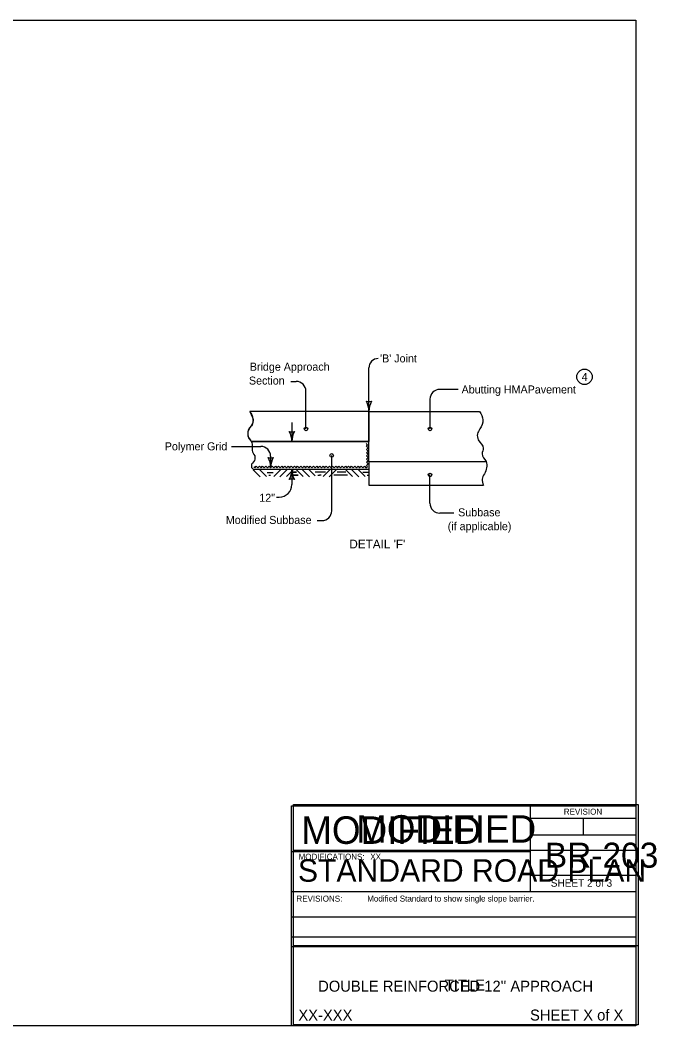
# Model space of a CAD drawing. Extents: x -2134934 to -2124557, y -2139046 to -2134021.
# Drawn here: x -2129429 to -2128157, y -2139046 to -2137036 of the extents above; entities that cross this region are included whole.
import ezdxf

# ---------------------------------------------------------------- set-up
doc = ezdxf.new("R2010")
doc.units = 0
for name, color, linetype in [('BridgeSuperStructureExisting', 7, 'Continuous'), ('Default', 7, 'Continuous'), ('Dimension', 7, 'Continuous'), ('dsnAlignmentCurveData', 7, 'Continuous'), ('dsnAlignmentStation', 7, 'Continuous'), ('DsnShtInsideBorder', 7, 'Continuous'), ('dsnStdLabel', 7, 'Continuous'), ('TC_Barrier', 7, 'Continuous')]:
    doc.layers.add(name, color=color, linetype=linetype)

msp = doc.modelspace()

# ---------------------------------------------------------------- linework, layer by layer
at = {"layer": 'BridgeSuperStructureExisting'}
for p, q in [((-2128732.5, -2137817.8), (-2128732.5, -2137731)), ((-2128888.8, -2137758), (-2128878.2, -2137758)), ((-2128858.4, -2137853), (-2128858.4, -2137777.8)), ((-2128554.4, -2137773.9), (-2128590.9, -2137773.9)), ((-2128610.7, -2137793.7), (-2128610.7, -2137853)), ((-2128732.5, -2137818.3), (-2128970.5, -2137818.3)), ((-2128732.5, -2137818.3), (-2128970.2, -2137818.3)), ((-2128732.5, -2137878.3), (-2128732.5, -2137818.3)), ((-2128732.5, -2137818.3), (-2128511.5, -2137818.3)), ((-2128732.5, -2137818.3), (-2128732.5, -2137878.3)), ((-2128886.6, -2137839.9), (-2128886.6, -2137878.3)), ((-2129007.2, -2137887.9), (-2128948.7, -2137887.9)), ((-2128967.4, -2137878.3), (-2128732.5, -2137878.3)), ((-2128732.5, -2137878.3), (-2128967.4, -2137878.3)), ((-2128732.5, -2137918.3), (-2128732.5, -2137878.3)), ((-2128928.9, -2137907.7), (-2128928.9, -2137929.9)), ((-2128806.9, -2138016.4), (-2128806.9, -2137905.9)), ((-2128732.9, -2137906.8), (-2128732.9, -2137906.8)), ((-2128732.5, -2137918.3), (-2128498.7, -2137918.3)), ((-2128732.5, -2137918.3), (-2128732.5, -2137965.6)), ((-2128963.8, -2137934.4), (-2128949.8, -2137948.4)), ((-2128732.9, -2137934.2), (-2128960.5, -2137934.2)), ((-2128930, -2137934.2), (-2128958.4, -2137934.2)), ((-2128951.4, -2137934.2), (-2128937.4, -2137948.2)), ((-2128924, -2137940.4), (-2128935.9, -2137940.4)), ((-2128932.4, -2137945.3), (-2128929.1, -2137945.3)), ((-2128930, -2137934.2), (-2128930, -2137934.2)), ((-2128831.5, -2137934.2), (-2128930, -2137934.2)), ((-2128930, -2137934.2), (-2128930, -2137934.2)), ((-2128908.6, -2137934.2), (-2128922.6, -2137948.2)), ((-2128896.3, -2137934.4), (-2128910.3, -2137948.4)), ((-2128883.4, -2137934.2), (-2128897.4, -2137948.2)), ((-2128887.8, -2137945.4), (-2128873.7, -2137945.4)), ((-2128887.8, -2137945.4), (-2128873.7, -2137945.4)), ((-2128873.7, -2137945.4), (-2128887.8, -2137945.4)), ((-2128873.7, -2137945.4), (-2128887.8, -2137945.4)), ((-2128886.6, -2137933.9), (-2128886.6, -2137964.1)), ((-2128884, -2137939.6), (-2128877.5, -2137939.6)), ((-2128884, -2137939.6), (-2128877.5, -2137939.6)), ((-2128877.5, -2137939.6), (-2128884, -2137939.6)), ((-2128877.5, -2137939.6), (-2128884, -2137939.6)), ((-2128878.1, -2137934.2), (-2128864.1, -2137948.2)), ((-2128865.2, -2137934.4), (-2128851.2, -2137948.4)), ((-2128852.9, -2137934.2), (-2128840, -2137947)), ((-2128819.6, -2137939.6), (-2128839.8, -2137939.6)), ((-2128834.7, -2137945.3), (-2128831.5, -2137945.3)), ((-2128831.5, -2137934.2), (-2128831.5, -2137934.2)), ((-2128732.9, -2137934.2), (-2128831.5, -2137934.2)), ((-2128831.5, -2137934.2), (-2128831.5, -2137934.2)), ((-2128828.3, -2137945.3), (-2128831.5, -2137945.3)), ((-2128828.3, -2137945.3), (-2128828.3, -2137945.3)), ((-2128810.1, -2137934.2), (-2128824.1, -2137948.2)), ((-2128822.5, -2137939.6), (-2128822.5, -2137939.6)), ((-2128797.8, -2137934.4), (-2128811.8, -2137948.4)), ((-2128775.2, -2137945.4), (-2128803, -2137945.4)), ((-2128779, -2137939.6), (-2128796.1, -2137939.6)), ((-2128779, -2137939.6), (-2128783.9, -2137939.6)), ((-2128779.5, -2137934.2), (-2128765.5, -2137948.2)), ((-2128766.7, -2137934.4), (-2128752.7, -2137948.4)), ((-2128754.3, -2137934.2), (-2128740.3, -2137948.2)), ((-2128744.8, -2137939.6), (-2128732.9, -2137939.6)), ((-2128741.9, -2137939.6), (-2128741.9, -2137939.6)), ((-2128736.2, -2137945.3), (-2128736.2, -2137945.3)), ((-2128736.2, -2137945.3), (-2128732.9, -2137945.3)), ((-2128610.7, -2138001.4), (-2128610.7, -2137945)), ((-2128732.5, -2137965.6), (-2128503.6, -2137965.6)), ((-2128917.2, -2137989.1), (-2128911.6, -2137989.1)), ((-2128562.9, -2138021.2), (-2128590.9, -2138021.2)), ((-2128835.8, -2138036.2), (-2128826.7, -2138036.2))]:
    msp.add_line(p, q, dxfattribs=at)
for points in [[(-2128735.2, -2137884.9), (-2128737.8, -2137882.3)], [(-2128735.7, -2137927.8), (-2128737.6, -2137925.9), (-2128734.4, -2137922.7), (-2128737.6, -2137919.5), (-2128734.4, -2137916.4), (-2128737.6, -2137913.2), (-2128734.4, -2137910), (-2128737.6, -2137906.9), (-2128734.4, -2137903.7), (-2128737.6, -2137900.5), (-2128734.4, -2137897.4), (-2128737.5, -2137894.2), (-2128734.4, -2137891), (-2128737.5, -2137887.9), (-2128735.2, -2137884.9)], [(-2128962.3, -2137928.8), (-2128960.7, -2137930.4), (-2128957.6, -2137927.2), (-2128954.4, -2137930.4), (-2128951.2, -2137927.2), (-2128948.1, -2137930.4), (-2128944.9, -2137927.3), (-2128941.7, -2137930.4), (-2128938.5, -2137927.3), (-2128935.4, -2137930.5), (-2128932.2, -2137927.3), (-2128929, -2137930.5), (-2128925.9, -2137927.3), (-2128922.7, -2137930.5), (-2128919.5, -2137927.3), (-2128916.4, -2137930.5), (-2128913.2, -2137927.3), (-2128910, -2137930.5), (-2128906.9, -2137927.4), (-2128903.7, -2137930.5), (-2128900.5, -2137927.4), (-2128897.4, -2137930.5), (-2128894.2, -2137927.4), (-2128891, -2137930.6), (-2128887.9, -2137927.4), (-2128886.4, -2137928.5)], [(-2128886.1, -2137928.9), (-2128884.5, -2137930.5), (-2128881.3, -2137927.4), (-2128878.2, -2137930.5), (-2128875, -2137927.4), (-2128871.8, -2137930.6), (-2128868.7, -2137927.4), (-2128865.5, -2137930.6), (-2128862.3, -2137927.4), (-2128859.2, -2137930.6), (-2128856, -2137927.4), (-2128852.8, -2137930.6), (-2128849.7, -2137927.4), (-2128846.5, -2137930.6), (-2128843.3, -2137927.5), (-2128840.2, -2137930.6), (-2128837, -2137927.5), (-2128833.8, -2137930.7), (-2128830.7, -2137927.5), (-2128827.5, -2137930.7), (-2128824.3, -2137927.5), (-2128821.2, -2137930.7), (-2128818, -2137927.5), (-2128814.8, -2137930.7), (-2128811.6, -2137927.5), (-2128810.2, -2137928.7)], [(-2128809.8, -2137929), (-2128808.3, -2137930.5), (-2128805.1, -2137927.4), (-2128801.9, -2137930.6), (-2128798.7, -2137927.4), (-2128795.6, -2137930.6), (-2128792.4, -2137927.4), (-2128789.2, -2137930.6), (-2128786.1, -2137927.4), (-2128782.9, -2137930.6), (-2128779.7, -2137927.5), (-2128776.6, -2137930.6), (-2128773.4, -2137927.5), (-2128770.2, -2137930.7), (-2128767.1, -2137927.5), (-2128763.9, -2137930.7), (-2128760.7, -2137927.5), (-2128757.6, -2137930.7), (-2128754.4, -2137927.5), (-2128751.2, -2137930.7), (-2128748.1, -2137927.5), (-2128744.9, -2137930.7), (-2128741.7, -2137927.6), (-2128738.6, -2137930.7), (-2128735.7, -2137927.8)]]:
    msp.add_lwpolyline(points, dxfattribs=at)
msp.add_circle((-2128302, -2137748.9), 15.4, dxfattribs=at)
for centre, radius, start, end in [((-2128714, -2137731), 18.6, 90, 180), ((-2128878.2, -2137777.8), 19.8, 0, 90), ((-2128590.9, -2137793.7), 19.8, 90, 180), ((-2128732.5, -2137781.9), 16.5, 252.2666, 287.7333), ((-2128775.3, -2137817.8), 42.7, 360, 28.0725), ((-2128732.5, -2137781.9), 16.5, 252.2666, 287.7333), ((-2128775.3, -2137817.8), 42.7, 360, 28.0725), ((-2128689.8, -2137817.8), 42.7, 151.9275, 180), ((-2128689.8, -2137817.8), 42.7, 151.9275, 180), ((-2128886.6, -2137842.5), 16.5, 252.2666, 287.7333), ((-2128929.3, -2137878.3), 42.7, 360, 28.0725), ((-2128843.8, -2137878.3), 42.7, 151.9275, 180), ((-2128948.7, -2137907.7), 19.8, 0, 90), ((-2128928.9, -2137894.1), 16.5, 252.2667, 287.7334), ((-2128971.6, -2137929.9), 42.7, 0, 28.0725), ((-2128886.1, -2137929.9), 42.7, 151.9275, 180), ((-2128929.3, -2137933.9), 42.7, 331.9275, 360), ((-2128843.8, -2137933.9), 42.7, 180, 208.0725), ((-2128911.6, -2137964.1), 25, 270, 0), ((-2128886.6, -2137969.8), 16.5, 72.2666, 107.7334), ((-2128590.9, -2138001.4), 19.8, 180, 270), ((-2128826.7, -2138016.4), 19.8, 270, 360)]:
    msp.add_arc(centre, radius, start, end, dxfattribs=at)
for points in [[(-2128970.5, -2137817.5), (-2128964.4, -2137832.8), (-2128964.6, -2137839.8), (-2128974.4, -2137859), (-2128972.9, -2137870.3), (-2128966.5, -2137880.4), (-2128965.9, -2137895.9), (-2128960.5, -2137906.8)], [(-2128511.5, -2137818.3), (-2128505, -2137834.7), (-2128511.1, -2137852.9), (-2128515.7, -2137862.8), (-2128514.1, -2137875), (-2128504.3, -2137891.7), (-2128506.5, -2137902.4), (-2128498.7, -2137918.3), (-2128502, -2137942.7), (-2128506.5, -2137953.3), (-2128503.6, -2137965.6)], [(-2128960.5, -2137906.8), (-2128960.5, -2137913.3), (-2128967, -2137923.5)], [(-2128967, -2137923.5), (-2128967, -2137929.9), (-2128960.5, -2137934.2)]]:
    msp.add_spline(points, degree=3, dxfattribs=at)
msp.add_open_spline([(-2128970.2, -2137818.3), (-2128968.3, -2137823.1), (-2128966.4, -2137828), (-2128964.4, -2137832.8), (-2128963.6, -2137835), (-2128964.1, -2137837.6), (-2128964.6, -2137839.8), (-2128966, -2137846.7), (-2128973.2, -2137852.3), (-2128974.4, -2137859), (-2128975, -2137862.6), (-2128974.3, -2137866.8), (-2128972.9, -2137870.3), (-2128971.8, -2137873.3), (-2128969.1, -2137875.6), (-2128967.4, -2137878.3)], degree=3, dxfattribs=at)
at = {"layer": 'Dimension'}
for p, q in [((-2128410.4, -2138605.9), (-2128410.4, -2138697.3)), ((-2128410.4, -2138630.9), (-2128199.4, -2138630.9)), ((-2128304.9, -2138630.9), (-2128304.9, -2138664.1)), ((-2128410.4, -2138664.1), (-2128199.4, -2138664.1)), ((-2128887.5, -2138697.3), (-2128410.4, -2138697.3)), ((-2128410.4, -2138697.3), (-2128410.4, -2138777.3)), ((-2128199.4, -2138745.1), (-2128410.4, -2138745.1)), ((-2128887.5, -2138777.3), (-2128199.4, -2138777.3)), ((-2128887.5, -2138828.3), (-2128199.4, -2138828.3)), ((-2128887.5, -2138868.3), (-2128199.4, -2138868.3)), ((-2128887.5, -2138887.3), (-2128199.4, -2138887.3))]:
    msp.add_line(p, q, dxfattribs=at)
msp.add_lwpolyline([(-2128887.5, -2138605.9), (-2128199.4, -2138605.9), (-2128199.4, -2139045.9), (-2128887.5, -2139045.9)], close=True, dxfattribs=at)
at = {"layer": 'dsnAlignmentStation'}
msp.add_lwpolyline([(-2131334.4, -2137035.9), (-2128199.4, -2137035.9), (-2128199.4, -2139045.9), (-2131334.4, -2139045.9)], close=True, dxfattribs=at)
at = {"layer": 'DsnShtInsideBorder'}
for p, q in [((-2128883.1, -2138695), (-2128195.1, -2138695)), ((-2128883.1, -2138885), (-2128195.1, -2138885))]:
    msp.add_line(p, q, dxfattribs=at)
msp.add_lwpolyline([(-2128883.1, -2138603.7), (-2128195.1, -2138603.7), (-2128195.1, -2139043.7), (-2128883.1, -2139043.7)], close=True, dxfattribs=at)
at = {"layer": 'TC_Barrier'}
for centre in [(-2128858.4, -2137853), (-2128610.7, -2137853), (-2128806.9, -2137905.9), (-2128610.7, -2137945)]:
    msp.add_circle(centre, 3.54, dxfattribs=at)

# ---------------------------------------------------------------- texts
at = {"layer": 'BridgeSuperStructureExisting'}
msp.add_text("DETAIL 'F'", height=17.5, dxfattribs=at).set_placement((-2128771.7, -2138091.7))
at = {"layer": 'Default'}
msp.add_text('MODIFIED', height=55, dxfattribs=at).set_placement((-2128867.8, -2138682.2))
at = {"layer": 'Dimension'}
for s, height, p in [('REVISION', 12, (-2128343.4, -2138623.8)), ('BR-203', 50, (-2128381.2, -2138729.8)), ('STANDARD ROAD PLAN', 45.001, (-2128874.4, -2138757.9)), ('SHEET 2 of 3', 15, (-2128369.4, -2138767.9)), ('Modified Standard to show single slope barrier.', 12, (-2128736.1, -2138797.5)), ("DOUBLE REINFORCED 12'' APPROACH", 22, (-2128834, -2138977.6))]:
    msp.add_text(s, height=height, dxfattribs=at).set_placement(p)
at = {"layer": 'dsnAlignmentCurveData'}
msp.add_text('REVISIONS:', height=12, dxfattribs=at).set_placement((-2128877.5, -2138797.6))
at = {"layer": 'DsnShtInsideBorder'}
for s, height, p in [('MODIFIED', 55, (-2128758.1, -2138679.9)), ('MODIFICATIONS:', 12, (-2128873.1, -2138713.9)), ('XX', 12, (-2128729.9, -2138713.9)), ('TITLE', 22, (-2128581.1, -2138975.4)), ('XX-XXX', 22, (-2128873.5, -2139035.3)), ('SHEET X of X', 22, (-2128410.8, -2139035.3))]:
    msp.add_text(s, height=height, dxfattribs=at).set_placement(p)
at = {"layer": 'dsnStdLabel'}
for s, p in [("'B' Joint", (-2128710.4, -2137720)), ('Bridge Approach', (-2128970.5, -2137736.6)), ('Section', (-2128972.3, -2137764.3)), ('4', (-2128307.6, -2137756.9)), ('Abutting HMAPavement', (-2128547.5, -2137782.1)), ('Polymer Grid', (-2129140.4, -2137895.7)), ('12"', (-2128951.6, -2137998.6)), ('Subbase', (-2128554.4, -2138027.6)), ('Modified Subbase', (-2129018.5, -2138042.8)), ('(if applicable)', (-2128575.2, -2138055.3))]:
    msp.add_text(s, height=16, dxfattribs=at).set_placement(p)

doc.saveas('drawing.dxf')
